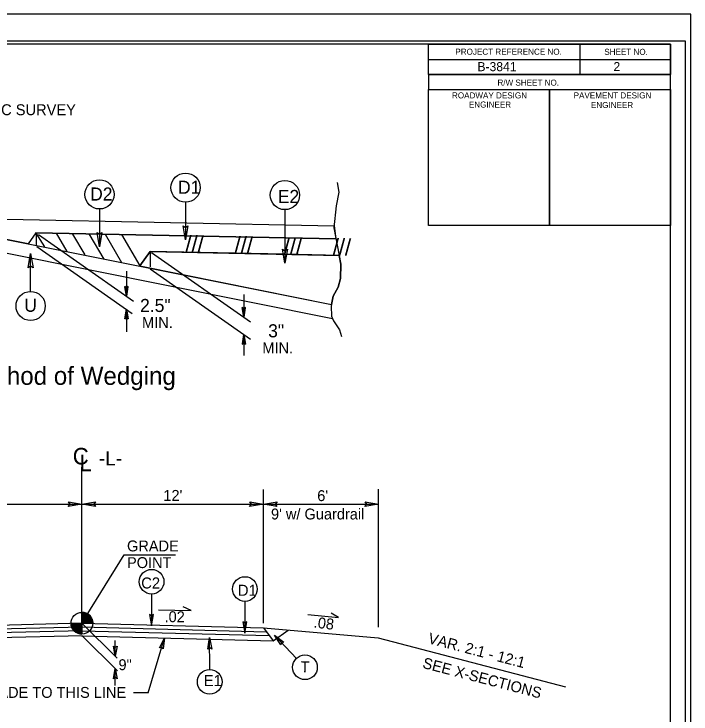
# Model space of a CAD drawing. Extents: x 193555 to 203883, y 190245 to 194645.
# Drawn here: x 198052 to 200291, y 192328 to 194645 of the extents above; entities that cross this region are included whole.
import ezdxf

# ---------------------------------------------------------------- set-up
doc = ezdxf.new("R2010")
doc.units = 0
for name, color, linetype in [('Old_Level_1', 7, 'Continuous'), ('Old_Level_11', 7, 'Continuous'), ('Old_Level_18', 7, 'Continuous'), ('Old_Level_2', 7, 'Continuous'), ('Old_Level_20', 7, 'Continuous'), ('Old_Level_40', 7, 'Continuous'), ('Old_Level_44', 7, 'Continuous'), ('Old_Level_50', 7, 'Continuous'), ('Old_Level_51', 7, 'Continuous'), ('Old_Level_52', 7, 'Continuous'), ('Prop Terminator CELL', 7, 'Continuous'), ('Typical Detail Wedge2 CELL', 7, 'Continuous'), ('Typical ID Circle CELL', 7, 'Continuous'), ('Typical Terminator CELL', 7, 'Continuous'), ('Typical Text Centerline CELL', 7, 'Continuous'), ('Typical Text General CELL', 7, 'Continuous'), ('Typical Text ID Circle CELL', 7, 'Continuous')]:
    doc.layers.add(name, color=color, linetype=linetype)

msp = doc.modelspace()

# ---------------------------------------------------------------- linework, layer by layer
at = {"layer": 'Old_Level_1'}
for p, q in [((200273.1, 194555), (200273.1, 194555)), ((198276.4, 192628.6), (198276.4, 193145.1)), ((198876.4, 192628.6), (198876.4, 193071.7)), ((199257.8, 192615.7), (199257.8, 193072.6)), ((197676.4, 193022.8), (198276.4, 193022.8)), ((198276.4, 193022.8), (198876.4, 193022.8)), ((198876.4, 193022.8), (199257.8, 193022.8)), ((198276.4, 192628.6), (198415.9, 192855.2)), ((198415.9, 192855.2), (198585.9, 192855.2)), ((198529.9, 192672.6), (198637.2, 192671)), ((198637.2, 192671), (198611.2, 192682.4)), ((198276.4, 192628.6), (198276.4, 192664.6)), ((199023.9, 192657.6), (199124.7, 192647.8)), ((199124.7, 192647.8), (199100.3, 192662.4)), ((198276.4, 192628.6), (197676.4, 192613.4)), ((198240.4, 192628.6), (198276.4, 192628.6)), ((198276.3, 192592.6), (198276.4, 192628.6)), ((198276.4, 192628.6), (198276.3, 192592.6)), ((198312.4, 192628.6), (198276.4, 192628.6)), ((198276.4, 192628.6), (198392.9, 192512.9)), ((198276.4, 192628.6), (198876.4, 192613.4)), ((198277, 192603.6), (197649.7, 192587.7)), ((198276.7, 192616.1), (197663, 192600.5)), ((198275.8, 192603.7), (198896, 192587.9)), ((198276.1, 192616.2), (198886.2, 192600.6)), ((198876.4, 192613.4), (199256.6, 192580.2)), ((198876.4, 192613.4), (198909, 192570.9)), ((198909, 192570.9), (198959, 192606.2)), ((198277.5, 192587), (197631.9, 192570.6)), ((198275.3, 192587), (198909, 192570.9)), ((198277.5, 192587), (198393.9, 192471.3)), ((198495, 192398.7), (198549.2, 192580.1)), ((199256.6, 192580.2), (199876.4, 192418.2)), ((198386.4, 192519.4), (198386.4, 192571.7)), ((198386.4, 192422.6), (198386.4, 192478.8)), ((198495, 192398.7), (198446.5, 192398.7))]:
    msp.add_line(p, q, dxfattribs=at)
for points in [[(198276.7, 192664.6), (198276.7, 192664.6), (198276.7, 192628.6)], [(198277.4, 192664.6), (198277.4, 192628.6)], [(198278.2, 192664.6), (198278.2, 192628.6)], [(198278.9, 192664.6), (198278.9, 192628.6)], [(198279.6, 192664.5), (198279.6, 192628.6)], [(198280.3, 192664.4), (198280.3, 192628.6)], [(198281, 192664.3), (198281, 192628.6)], [(198281.8, 192664.2), (198281.8, 192628.6)], [(198282.5, 192664.2), (198282.5, 192628.6)], [(198283.2, 192664), (198283.2, 192628.6)], [(198283.9, 192663.8), (198283.9, 192628.6)], [(198284.6, 192663.7), (198284.6, 192628.6)], [(198285.4, 192663.5), (198285.4, 192628.6)], [(198286.1, 192663.3), (198286.1, 192628.6)], [(198286.8, 192663.1), (198286.8, 192628.6)], [(198287.5, 192662.9), (198287.5, 192628.6)], [(198288.2, 192662.6), (198288.2, 192628.6)], [(198289, 192662.4), (198289, 192628.6)], [(198289.7, 192662.1), (198289.7, 192628.6)], [(198290.4, 192661.8), (198290.4, 192628.6)], [(198291.1, 192661.4), (198291.1, 192628.6)], [(198291.8, 192661.1), (198291.8, 192628.6)], [(198292.6, 192660.8), (198292.6, 192628.6)], [(198293.3, 192660.4), (198293.3, 192628.6)], [(198294, 192660), (198294, 192628.6)], [(198294.7, 192659.6), (198294.7, 192628.6)], [(198295.4, 192659.2), (198295.4, 192628.6)], [(198296.2, 192658.7), (198296.2, 192628.6)], [(198296.9, 192658.2), (198296.9, 192628.6)], [(198297.6, 192657.7), (198297.6, 192628.6)], [(198298.3, 192657.2), (198298.3, 192628.6)], [(198299, 192656.6), (198299, 192628.6)], [(198299.8, 192656), (198299.8, 192628.6)], [(198300.5, 192655.4), (198300.5, 192628.6)], [(198301.2, 192654.7), (198301.2, 192628.6)], [(198301.9, 192654), (198301.9, 192628.6)], [(198302.6, 192653.3), (198302.6, 192628.6)], [(198303.4, 192652.5), (198303.4, 192628.6)], [(198304.1, 192651.6), (198304.1, 192628.6)], [(198304.8, 192650.7), (198304.8, 192628.6)], [(198305.5, 192649.8), (198305.5, 192628.6)], [(198306.2, 192648.7), (198306.2, 192628.6)], [(198307, 192647.6), (198307, 192628.6)], [(198307.7, 192646.4), (198307.7, 192628.6)], [(198308.4, 192645.1), (198308.4, 192628.6)], [(198240.6, 192628.6), (198240.6, 192624.7)], [(198241.3, 192628.6), (198241.3, 192620.5)], [(198242, 192628.6), (198242, 192617.9)], [(198242.7, 192628.6), (198242.7, 192615.8)], [(198243.4, 192628.6), (198243.4, 192614.1)], [(198244.2, 192628.6), (198244.2, 192612.6)], [(198244.9, 192628.6), (198244.9, 192611.2)], [(198245.6, 192628.6), (198245.6, 192609.9)], [(198246.3, 192628.6), (198246.3, 192608.8)], [(198247, 192628.6), (198247, 192607.8)], [(198247.8, 192628.6), (198247.8, 192606.8)], [(198248.5, 192628.6), (198248.5, 192605.9)], [(198249.2, 192628.6), (198249.2, 192605)], [(198249.9, 192628.6), (198249.9, 192604.2)], [(198250.6, 192628.6), (198250.6, 192603.4)], [(198251.4, 192628.6), (198251.4, 192602.7)], [(198252.1, 192628.6), (198252.1, 192602.1)], [(198252.8, 192628.6), (198252.8, 192601.4)], [(198253.5, 192628.6), (198253.5, 192600.8)], [(198254.2, 192628.6), (198254.2, 192600.2)], [(198255, 192628.6), (198255, 192599.7)], [(198255.7, 192628.6), (198255.7, 192599.2)], [(198256.4, 192628.6), (198256.4, 192598.7)], [(198257.1, 192628.6), (198257.1, 192598.2)], [(198257.8, 192628.6), (198257.8, 192597.8)], [(198258.6, 192628.6), (198258.6, 192597.4)], [(198259.3, 192628.6), (198259.3, 192597)], [(198260, 192628.6), (198260, 192596.6)], [(198260.7, 192628.6), (198260.7, 192596.2)], [(198261.4, 192628.6), (198261.4, 192595.9)], [(198262.2, 192628.6), (198262.2, 192595.6)], [(198262.9, 192628.6), (198262.9, 192595.3)], [(198263.6, 192628.6), (198263.6, 192595)], [(198264.3, 192628.6), (198264.3, 192594.7)], [(198265, 192628.6), (198265, 192594.5)], [(198265.8, 192628.6), (198265.8, 192594.2)], [(198266.5, 192628.6), (198266.5, 192594.1)], [(198267.2, 192628.6), (198267.2, 192593.8)], [(198267.9, 192628.6), (198267.9, 192593.7)], [(198268.6, 192628.6), (198268.6, 192593.5)], [(198269.4, 192628.6), (198269.4, 192593.4)], [(198270.1, 192628.6), (198270.1, 192593.2)], [(198270.8, 192628.6), (198270.8, 192593.1)], [(198271.5, 192628.6), (198271.5, 192593)], [(198272.2, 192628.6), (198272.2, 192592.9)], [(198273, 192628.6), (198273, 192592.8)], [(198273.7, 192628.6), (198273.7, 192592.7)], [(198274.4, 192628.6), (198274.4, 192592.7)], [(198275.1, 192628.6), (198275.1, 192592.6)], [(198275.8, 192628.6), (198275.8, 192592.6), (198275.8, 192592.6)], [(198309.1, 192643.6), (198309.1, 192628.6)], [(198309.8, 192641.9), (198309.8, 192628.6)], [(198310.6, 192639.9), (198310.6, 192628.6)], [(198311.3, 192637.4), (198311.3, 192628.6)], [(198312, 192633.8), (198312, 192628.6)]]:
    msp.add_lwpolyline(points, dxfattribs=at)
msp.add_circle((198276.4, 192628.6), 36, dxfattribs=at)
for start, end in [(359.9905, 89.9905), (179.9905, 269.9905)]:
    msp.add_arc((198276.4, 192628.6), 36, start, end, dxfattribs=at)
at = {"layer": 'Old_Level_11'}
for p, q in [((198506.6, 192725.3), (198506.6, 192619.8)), ((198815.4, 192701.1), (198815.3, 192595.6)), ((198698.9, 192475.6), (198698.8, 192581.1)), ((198986.1, 192512.4), (198913.5, 192589))]:
    msp.add_line(p, q, dxfattribs=at)
for points in [[(198231.4, 193030.5), (198276.4, 193022.8), (198231.1, 193014.8), (198236.9, 193022.8)], [(198321.4, 193015), (198276.4, 193022.8), (198321.7, 193030.7), (198315.9, 193022.7)], [(198831.4, 193030.5), (198876.4, 193022.8), (198831.1, 193014.8), (198836.9, 193022.8)], [(198921.4, 193015), (198876.4, 193022.8), (198921.7, 193030.7), (198915.9, 193022.7)], [(199212.8, 193030.5), (199257.8, 193022.8), (199212.6, 193014.8), (199218.3, 193022.8)], [(198500.1, 192657.6), (198506.6, 192619.8), (198513.3, 192657.8), (198506.6, 192653)], [(198808.8, 192633.4), (198815.3, 192595.6), (198822.1, 192633.6), (198815.4, 192628.8)], [(198692.3, 192543.3), (198698.8, 192581.1), (198705.6, 192543.1), (198698.8, 192547.9)], [(198934.8, 192557.1), (198913.5, 192589), (198944.5, 192566), (198936.3, 192564.9)], [(198392.4, 192553.1), (198386.4, 192519.4), (198380.6, 192553.3), (198386.6, 192549)], [(198381.1, 192444.9), (198386.4, 192478.8), (198392.9, 192444.9), (198386.9, 192449.1)]]:
    msp.add_lwpolyline(points, close=True, dxfattribs=at)
for centre in [(198506.7, 192766.1), (198815.4, 192741.9), (199014.1, 192482.8), (198698.9, 192434.7)]:
    msp.add_circle(centre, 40.8, dxfattribs=at)
at = {"layer": 'Old_Level_18'}
msp.add_lwpolyline([(200223.1, 194544.8), (194223.1, 194544.8), (194223.1, 190344.8), (200223.1, 190344.8)], close=True, dxfattribs=at)
at = {"layer": 'Old_Level_40'}
for p, q in [((199923.1, 194544.6), (199923.1, 194444.6)), ((199422.9, 194494.6), (200223.1, 194494.6)), ((199422.9, 194444.6), (200223.1, 194444.6)), ((199422.9, 194444.6), (199422.9, 194394.6)), ((199422.9, 194444.6), (200223.1, 194444.6)), ((199823.1, 194394.6), (199823.1, 193944.8))]:
    msp.add_line(p, q, dxfattribs=at)
for points in [[(199422.9, 194544.8), (200223.1, 194544.8), (200223.1, 194444.6), (199422.9, 194444.6)], [(199422.9, 194394.6), (199823.1, 194394.6), (199823.1, 193944.6), (199422.9, 193944.6)], [(199823.1, 194394.6), (200223.1, 194394.6), (200223.1, 193944.6), (199823.1, 193944.6)]]:
    msp.add_lwpolyline(points, close=True, dxfattribs=at)
at = {"layer": 'Old_Level_50'}
msp.add_line((200291.1, 194644.8), (200291.1, 194644.8), dxfattribs=at)
msp.add_lwpolyline([(200273.1, 194555), (193607.1, 194555), (193607.1, 190334.6), (200273.1, 190334.6)], close=True, dxfattribs=at)
at = {"layer": 'Old_Level_51'}
msp.add_lwpolyline([(200291.1, 194644.8), (193555.1, 194644.8), (193555.1, 190244.8), (200291.1, 190244.8)], close=True, dxfattribs=at)
at = {"layer": 'Old_Level_52'}
msp.add_line((200273.1, 194555), (200273.1, 194555), dxfattribs=at)
at = {"layer": 'Prop Terminator CELL'}
msp.add_lwpolyline([(198532.9, 192547.4), (198549.2, 192580.1), (198545, 192543.6), (198540.1, 192549.8)], close=True, dxfattribs=at)
at = {"layer": 'Typical Detail Wedge2 CELL'}
for p, q in [((198028.2, 193965.6), (199110.5, 193944)), ((198028.3, 193965.6), (199110.5, 193944)), ((199110.5, 193944), (199116.7, 193900.5)), ((198123.9, 193920.4), (198098.8, 193884.7)), ((198123.9, 193920.4), (198098.8, 193884.7)), ((198122.3, 193919.6), (198123.9, 193919.5)), ((198123.9, 193920.4), (199116.7, 193900.5)), ((199116.7, 193900.5), (198123.9, 193920.4)), ((198153.9, 193874.1), (198124.6, 193920)), ((198124.6, 193920), (198124.6, 193878.5)), ((198191.3, 193919.5), (198226.7, 193859)), ((198026.6, 193899.1), (199102.3, 193683.9)), ((198098.8, 193884.7), (198026.6, 193899.1)), ((198132.2, 193914.6), (198446.4, 193694.6)), ((198245.6, 193916.7), (198286.1, 193847.4)), ((198299.5, 193916.9), (198348.4, 193833.1)), ((198353, 193915.8), (198407.5, 193822.4)), ((198407.1, 193914.7), (198467.6, 193810.9)), ((198127.3, 193875), (198442.9, 193654.1)), ((198028.6, 193852.8), (199105.2, 193637.4)), ((198501.6, 193858.6), (198467.6, 193810.9)), ((198467.7, 193810.9), (198501.6, 193858.6)), ((198501.6, 193858.6), (199127.2, 193846)), ((198501.6, 193858.6), (198501.6, 193807.8)), ((198947.7, 193849.6), (198501.6, 193858.6)), ((198506.7, 193855), (198834.3, 193625.6)), ((199127.2, 193846), (198947.7, 193849.6)), ((198467.6, 193810.9), (198610.6, 193782.3)), ((198423.4, 193793.9), (198423.4, 193710.7)), ((198501.6, 193801.2), (198833.7, 193568.6)), ((198610.6, 193782.3), (199102.3, 193683.9)), ((198423.4, 193710.7), (198417.8, 193742.6)), ((198423.4, 193738.4), (198417.8, 193742.6)), ((198423.4, 193710.7), (198418.6, 193742)), ((198419.4, 193741.4), (198423.4, 193710.7)), ((198423.4, 193710.7), (198420.2, 193740.8)), ((198421, 193740.2), (198423.4, 193710.7)), ((198423.4, 193710.7), (198421.8, 193739.6)), ((198422.6, 193739), (198423.4, 193710.7)), ((198423.4, 193710.7), (198429, 193742.6)), ((198429, 193742.6), (198423.4, 193738.4)), ((198428.2, 193742), (198423.4, 193710.7)), ((198423.4, 193710.7), (198427.4, 193741.4)), ((198426.6, 193740.8), (198423.4, 193710.7)), ((198423.4, 193710.7), (198425.8, 193740.2)), ((198425, 193739.6), (198423.4, 193710.7)), ((198423.4, 193710.7), (198424.2, 193739)), ((198423.4, 193738.4), (198423.4, 193710.7)), ((198811.7, 193716.6), (198811.7, 193641.4)), ((198423.4, 193667.7), (198417.8, 193635.8)), ((198418.6, 193636.5), (198423.4, 193667.7)), ((198423.4, 193667.7), (198419.4, 193637)), ((198420.2, 193637.7), (198423.4, 193667.7)), ((198423.4, 193667.7), (198421, 193638.2)), ((198421.8, 193638.8), (198423.4, 193667.7)), ((198423.4, 193667.7), (198422.6, 193639.4)), ((198423.4, 193667.7), (198423.4, 193593.3)), ((198423.4, 193667.7), (198429, 193635.8)), ((198423.4, 193640), (198423.4, 193667.7)), ((198424.2, 193639.4), (198423.4, 193667.7)), ((198423.4, 193667.7), (198425, 193638.8)), ((198425.8, 193638.2), (198423.4, 193667.7)), ((198423.4, 193667.7), (198426.6, 193637.7)), ((198427.4, 193637), (198423.4, 193667.7)), ((198423.4, 193667.7), (198428.2, 193636.5)), ((198811.7, 193641.4), (198806.1, 193673.2)), ((198811.7, 193669.1), (198806.1, 193673.2)), ((198811.7, 193641.4), (198806.9, 193672.6)), ((198807.7, 193672.1), (198811.7, 193641.4)), ((198811.7, 193641.4), (198808.5, 193671.5)), ((198809.3, 193670.9), (198811.7, 193641.4)), ((198811.7, 193641.4), (198810.1, 193670.3)), ((198810.9, 193669.7), (198811.7, 193641.4)), ((198811.7, 193641.4), (198817.4, 193673.2)), ((198817.4, 193673.2), (198811.7, 193669.1)), ((198816.5, 193672.6), (198811.7, 193641.4)), ((198811.7, 193641.4), (198815.7, 193672.1)), ((198814.9, 193671.5), (198811.7, 193641.4)), ((198811.7, 193641.4), (198814.1, 193670.9)), ((198813.3, 193670.3), (198811.7, 193641.4)), ((198811.7, 193641.4), (198812.5, 193669.7)), ((198811.7, 193669.1), (198811.7, 193641.4)), ((198417.8, 193635.8), (198423.4, 193640)), ((198423.4, 193640), (198429, 193635.8)), ((198811.7, 193584), (198806.1, 193552.2)), ((198806.9, 193552.8), (198811.7, 193584)), ((198811.7, 193584), (198807.7, 193553.4)), ((198808.5, 193554), (198811.7, 193584)), ((198811.7, 193584), (198809.3, 193554.6)), ((198810.1, 193555.2), (198811.7, 193584)), ((198811.7, 193584), (198810.9, 193555.8)), ((198811.7, 193584), (198811.7, 193514.2)), ((198811.7, 193584), (198817.4, 193552.2)), ((198811.7, 193556.4), (198811.7, 193584)), ((198812.5, 193555.8), (198811.7, 193584)), ((198811.7, 193584), (198813.3, 193555.2)), ((198814.1, 193554.6), (198811.7, 193584)), ((198811.7, 193584), (198814.9, 193554)), ((198815.7, 193553.4), (198811.7, 193584)), ((198811.7, 193584), (198816.5, 193552.8)), ((198806.1, 193552.2), (198811.7, 193556.4)), ((198811.7, 193556.4), (198817.4, 193552.2))]:
    msp.add_line(p, q, dxfattribs=at)
for points in [[(199120.5, 194086.9), (199126.3, 194055.1), (199117.6, 194010.1), (199109.9, 193937.1), (199120.5, 193879.5), (199133, 193817.1), (199132, 193770), (199124.3, 193740.3), (199107, 193710.5), (199101.3, 193677.9), (199102.2, 193645.3), (199108, 193629.9), (199128.1, 193599.2), (199134.8, 193578)], [(199102.3, 193683.9), (199107, 193710.5), (199124.3, 193740.3), (199132, 193770), (199133, 193817.1), (199127.2, 193846)]]:
    msp.add_lwpolyline(points, dxfattribs=at)
at = {"layer": 'Typical ID Circle CELL'}
for p, q in [((198619.1, 194021.9), (198619.1, 193897)), ((198334.5, 193999.5), (198334.5, 193874.6)), ((198947.7, 193997.4), (198947.7, 193819.8)), ((198106.5, 193726.8), (198106.5, 193851.7))]:
    msp.add_line(p, q, dxfattribs=at)
for centre in [(198619.1, 194070.2), (198334.5, 194047.8), (198947.7, 194045.7), (198106.5, 193678.5)]:
    msp.add_circle(centre, 48.3, dxfattribs=at)
at = {"layer": 'Typical Terminator CELL'}
for points in [[(198627.1, 193943.9), (198619.1, 193897), (198610.7, 193944.1), (198619.1, 193938.1)], [(198627.1, 193943.9), (198619.1, 193897), (198610.7, 193944.1), (198619.1, 193938.1)], [(198342.6, 193921.5), (198334.5, 193874.6), (198326.2, 193921.7), (198334.5, 193915.7)], [(198342.6, 193921.5), (198334.5, 193874.6), (198326.2, 193921.7), (198334.5, 193915.7)], [(198098.4, 193804.9), (198106.5, 193851.7), (198114.8, 193804.6), (198106.5, 193810.6)], [(198098.4, 193804.9), (198106.5, 193851.7), (198114.8, 193804.6), (198106.5, 193810.6)], [(198955.8, 193866.6), (198947.7, 193819.8), (198939.4, 193866.9), (198947.7, 193860.9)]]:
    msp.add_lwpolyline(points, close=True, dxfattribs=at)

# ---------------------------------------------------------------- texts
at = {"layer": 'Old_Level_1'}
for s, height, p in [('-L-', 46.8, (198332.4, 193150.9)), ("12'", 36, (198545.7, 193033.6)), ("6'", 36, (199054.7, 193032.8)), ("9' w/ Guardrail", 36, (198901.7, 192972.1)), ('GRADE', 36, (198425.4, 192866.4)), ('POINT', 36, (198425.4, 192811.2)), ('.02', 36, (198549.6, 192632.1)), ('9"', 36, (198397.2, 192473.4)), ('GRADE TO THIS LINE', 36, (197927.7, 192381.7))]:
    msp.add_text(s, height=height, dxfattribs=at).set_placement(p)
for s, rotation, p in [('.08', 353.496, (199041.7, 192614.4)), (' VAR. 2:1 - 12:1', 345.3515, (199405.9, 192566.3)), ('SEE X-SECTIONS', 345.3515, (199400.6, 192481.3))]:
    msp.add_text(s, height=36, rotation=rotation, dxfattribs=at).set_placement(p)
at = {"layer": 'Old_Level_2'}
msp.add_text('C', height=54.9, dxfattribs=at).set_placement((198245.8, 193154))
msp.add_text('L', height=54.9, rotation=359.9469, dxfattribs=at).set_placement((198267.9, 193131.8))
at = {"layer": 'Old_Level_20'}
for s, height, rotation, p in [('C2', 36.54, 359.9708, (198472.4, 192743.6)), ('D1', 36.54, 359.9708, (198792.2, 192719.4)), ('T', 36.5, 358.454, (198998.7, 192466.4)), ('E1', 36.54, 0.0292, (198679.2, 192420.7))]:
    msp.add_text(s, height=height, rotation=rotation, dxfattribs=at).set_placement(p)
at = {"layer": 'Old_Level_44'}
for s, height, p in [('PROJECT REFERENCE NO.', 20, (199511.7, 194510)), ('SHEET NO.', 20, (200004.3, 194509.6)), ('B-3841   ', 30, (199584.6, 194455.6)), ('2  ', 30, (200034.6, 194455.8)), ('R/W SHEET NO.', 20, (199650.9, 194407.8)), ('ROADWAY DESIGN', 20, (199500.5, 194365.4)), ('PAVEMENT DESIGN', 20, (199902.9, 194365.4)), ('ENGINEER', 20, (199556.3, 194335.2)), ('ENGINEER', 20, (199960.1, 194333.6))]:
    msp.add_text(s, height=height, dxfattribs=at).set_placement(p)
at = {"layer": 'Typical Detail Wedge2 CELL'}
for height, rotation, p in [(54.25, 358.8553, (198618.2, 193856.8)), (54.25, 358.8536, (198780.9, 193853.5)), (54.27, 358.8554, (198943.4, 193848.7)), (54.27, 358.8537, (199105.6, 193846.8))]:
    msp.add_text('/// ', height=height, rotation=rotation, dxfattribs=at).set_placement(p)
for s, height, p in [('2.5"', 43.27, (198468.7, 193658.6)), ('MIN.', 36.15, (198475, 193605.5)), ('3"', 43.27, (198892.3, 193574.8)), ('MIN.', 36.15, (198873, 193521.6))]:
    msp.add_text(s, height=height, dxfattribs=at).set_placement(p)
at = {"layer": 'Typical Text Centerline CELL'}
msp.add_text('C SURVEY ', height=36.15, dxfattribs=at).set_placement((198009.1, 194309.9))
at = {"layer": 'Typical Text General CELL'}
msp.add_text('Detail Showing Method of Wedging', height=59.678, dxfattribs=at).set_placement((197340.4, 193417.6))
at = {"layer": 'Typical Text ID Circle CELL'}
for s, height, p in [('D1', 43.27, (198594.2, 194049.8)), ('D2', 43.27, (198303.4, 194027.4)), ('E2', 43.27, (198924.2, 194019.4)), ('U', 43.3, (198085.4, 193659.3))]:
    msp.add_text(s, height=height, dxfattribs=at).set_placement(p)

doc.saveas('drawing.dxf')
